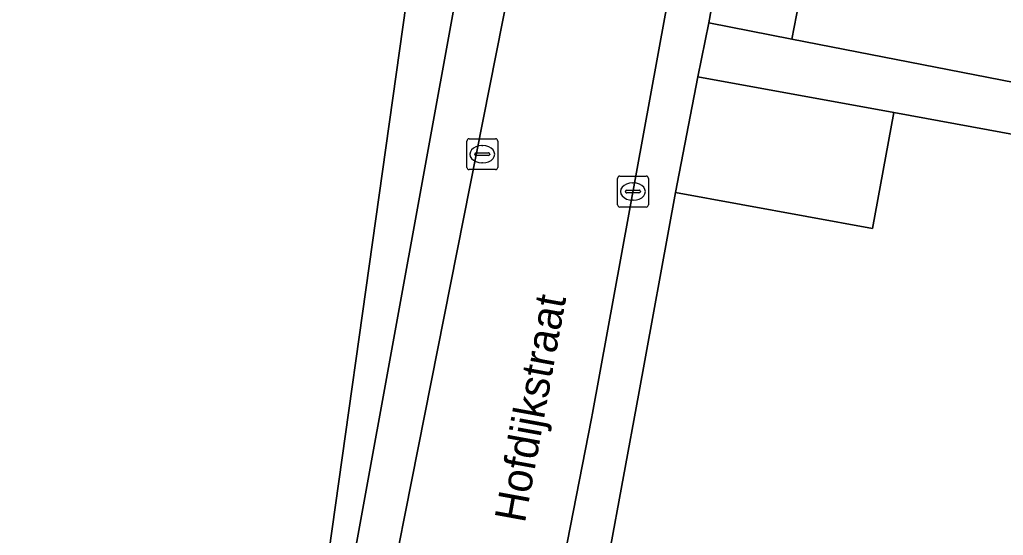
# Model space of a CAD drawing. Extents: x 161402 to 161933, y 381647 to 382315.
# Drawn here: x 161806.67 to 161838.49, y 381966.66 to 381983.35 of the extents above; entities that cross this region are included whole.
import ezdxf

# ---------------------------------------------------------------- set-up
doc = ezdxf.new("R2010")
doc.units = 0
for name, color, linetype in [('IMGEO_Erf', 7, 'Continuous'), ('IMGEO_Groenvoorziening', 7, 'Continuous'), ('IMGEO_Kolk', 7, 'Continuous'), ('IMGEO_Muur', 7, 'Continuous'), ('IMGEO_Openbare_ruimte_label', 7, 'Continuous'), ('IMGEO_Pand', 7, 'Continuous'), ('IMGEO_Parkeervlak_gesloten', 7, 'Continuous'), ('IMGEO_Rijbaan_lokaal_gesloten', 7, 'Continuous'), ('IMGEO_Rijbaan_lokaal_open', 7, 'Continuous'), ('IMGEO_Voetpad_open', 7, 'Continuous')]:
    doc.layers.add(name, color=color, linetype=linetype)

msp = doc.modelspace()

# ---------------------------------------------------------------- linework, layer by layer
at = {"layer": 'IMGEO_Erf'}
for points in [[(161781.596, 381964.647), (161815.795, 381959.903), (161829.294, 382055.793), (161829.439, 382055.781), (161829.897, 382055.72), (161832.064, 382072.53), (161836.652, 382071.701), (161840.585, 382094.002)], [(161839.466, 381979.518), (161834.946, 381980.346), (161834.257, 381976.588), (161827.883, 381977.756), (161826.684, 381971.203), (161825.719, 381965.932), (161832.204, 381964.716), (161838.276, 381963.578), (161838.779, 381966.265)]]:
    msp.add_lwpolyline(points, dxfattribs=at)
at = {"layer": 'IMGEO_Groenvoorziening'}
msp.add_lwpolyline([(161832.505, 382048.322), (161830.782, 382048.597), (161831.04, 382050.152), (161832.794, 382049.905), (161832.872, 382050.33), (161831.118, 382050.626), (161831.391, 382052.269), (161831.43, 382052.504), (161829.006, 382052.887), (161829.439, 382055.781), (161829.294, 382055.793), (161815.795, 381959.903), (161816.367, 381959.82), (161816.701, 381961.668), (161822.827, 381995.34)], close=True, dxfattribs=at)
at = {"layer": 'IMGEO_Kolk'}
for p, q in [((161821.134, 381978.571), (161821.134, 381979.423)), ((161821.209, 381979.497), (161822.061, 381979.497)), ((161822.135, 381979.423), (161822.135, 381978.571)), ((161821.393, 381978.991), (161821.393, 381979.003)), ((161821.436, 381979.04), (161821.834, 381979.04)), ((161821.622, 381979.277), (161821.647, 381979.277)), ((161821.877, 381979.003), (161821.877, 381978.991)), ((161821.831, 381978.954), (161821.433, 381978.954)), ((161821.645, 381978.717), (161821.62, 381978.717)), ((161822.061, 381978.497), (161821.209, 381978.497)), ((161826.008, 381977.362), (161826.008, 381978.214)), ((161826.083, 381978.288), (161826.935, 381978.288)), ((161826.496, 381978.068), (161826.521, 381978.068)), ((161827.009, 381978.214), (161827.009, 381977.362)), ((161826.267, 381977.782), (161826.267, 381977.794)), ((161826.705, 381977.745), (161826.307, 381977.745)), ((161826.31, 381977.831), (161826.708, 381977.831)), ((161826.751, 381977.794), (161826.751, 381977.782)), ((161826.519, 381977.508), (161826.494, 381977.508)), ((161826.935, 381977.288), (161826.083, 381977.288))]:
    msp.add_line(p, q, dxfattribs=at)
for points in [[(161821.134, 381978.571), (161821.134, 381979.423)], [(161821.209, 381979.497), (161822.061, 381979.497)], [(161822.135, 381979.423), (161822.135, 381978.571)], [(161822.061, 381978.497), (161821.209, 381978.497)], [(161826.008, 381977.362), (161826.008, 381978.214)], [(161826.083, 381978.288), (161826.935, 381978.288)], [(161827.009, 381978.214), (161827.009, 381977.362)], [(161826.935, 381977.288), (161826.083, 381977.288)]]:
    msp.add_lwpolyline(points, dxfattribs=at)
for centre, radius, start, end in [((161821.211, 381979.421), 0.0765, 91.552, 178.448), ((161821.211, 381979.421), 0.0765, 91.552, 178.448), ((161822.059, 381979.421), 0.0765, 1.552, 88.448), ((161822.059, 381979.421), 0.0765, 1.552, 88.448), ((161821.433, 381979), 0.0403, 85.8775, 175.7526), ((161821.43, 381978.99), 0.0366, 178.938, 274.7102), ((161821.834, 381978.997), 0.043, 264.8664, 352.4533), ((161821.838, 381979.002), 0.0386, 1.7309, 96.639), ((161821.211, 381978.573), 0.0765, 181.552, 268.448), ((161821.211, 381978.573), 0.0765, 181.552, 268.448), ((161822.059, 381978.573), 0.0765, 271.552, 358.448), ((161822.059, 381978.573), 0.0765, 271.552, 358.448), ((161826.085, 381978.212), 0.0765, 91.552, 178.448), ((161826.085, 381978.212), 0.0765, 91.552, 178.448), ((161826.933, 381978.212), 0.0765, 1.552, 88.448), ((161826.933, 381978.212), 0.0765, 1.552, 88.448), ((161826.307, 381977.791), 0.0403, 85.8775, 175.7526), ((161826.304, 381977.781), 0.0366, 178.938, 274.7102), ((161826.708, 381977.788), 0.043, 264.8664, 352.4533), ((161826.712, 381977.793), 0.0386, 1.7309, 96.639), ((161826.085, 381977.364), 0.0765, 181.552, 268.448), ((161826.085, 381977.364), 0.0765, 181.552, 268.448), ((161826.933, 381977.364), 0.0765, 271.552, 358.448), ((161826.933, 381977.364), 0.0765, 271.552, 358.448)]:
    msp.add_arc(centre, radius, start, end, dxfattribs=at)
for centre, major_axis, ratio, start_param, end_param in [((161821.621, 381978.997), (-0.387, 0.002), 0.722429, 4.712389, 7.853982), ((161821.646, 381978.997), (-0.39, 0.002), 0.717154, 1.570796, 4.712389), ((161826.495, 381977.788), (-0.387, 0.002), 0.722429, 4.712389, 7.853982), ((161826.52, 381977.788), (-0.39, 0.002), 0.717154, 1.570796, 4.712389)]:
    msp.add_ellipse(centre, major_axis=major_axis, ratio=ratio, start_param=start_param, end_param=end_param, dxfattribs=at)
at = {"layer": 'IMGEO_Muur'}
for points in [[(161827.883, 381977.756), (161826.684, 381971.203)], [(161826.684, 381971.203), (161825.719, 381965.932)]]:
    msp.add_lwpolyline(points, dxfattribs=at)
at = {"layer": 'IMGEO_Pand'}
msp.add_lwpolyline([(161827.883, 381977.756), (161834.257, 381976.588), (161834.946, 381980.346), (161828.609, 381981.506)], close=True, dxfattribs=at)
at = {"layer": 'IMGEO_Parkeervlak_gesloten'}
msp.add_lwpolyline([(161834.75, 381987.369), (161832.631, 381987.778), (161831.646, 381982.721), (161846.863, 381979.756), (161850.336, 381979.079), (161853.869, 381978.391), (161856.229, 381977.931), (161857.213, 381983.04)], close=True, dxfattribs=at)
at = {"layer": 'IMGEO_Rijbaan_lokaal_gesloten'}
msp.add_lwpolyline([(161834.474, 381994.007), (161830.987, 381994.574), (161828.968, 381983.243), (161831.646, 381982.721), (161832.631, 381987.778), (161834.75, 381987.369), (161857.213, 381983.04), (161856.229, 381977.931), (161861.321, 381976.94), (161861.636, 381978.805), (161862.491, 381983.458), (161857.448, 381984.357), (161864.341, 382023.003)], dxfattribs=at)
at = {"layer": 'IMGEO_Rijbaan_lokaal_open'}
for points in [[(161859.869, 382107.508), (161855.583, 382102.928), (161847.522, 382094.137), (161844.797, 382079.199), (161841.729, 382061.924), (161839.275, 382047.946), (161836.784, 382033.46), (161833.899, 382016.966), (161830.695, 382000), (161827.554, 381983.498), (161825.196, 381970.616), (161825.164, 381970.44), (161822.54, 381956.991), (161822.45, 381956.505), (161823.681, 381955.575), (161824.173, 381957.682), (161825.719, 381965.932), (161826.684, 381971.203), (161827.883, 381977.756), (161828.609, 381981.506), (161828.968, 381983.243), (161830.987, 381994.574), (161831.954, 382000), (161840.202, 382046.042)], [(161830.73, 382029.273), (161829.195, 382020.232), (161827.39, 382010.57), (161825.499, 382000), (161825.157, 381998.089), (161824.386, 381993.913), (161817.254, 381957.834), (161817.094, 381956.896), (161816.977, 381956.412), (161822.45, 381956.505), (161822.54, 381956.991), (161825.164, 381970.44), (161825.196, 381970.616), (161827.554, 381983.498), (161830.695, 382000), (161833.899, 382016.966), (161836.784, 382033.46)]]:
    msp.add_lwpolyline(points, dxfattribs=at)
msp.add_lwpolyline([(161827.39, 382010.57), (161829.195, 382020.232), (161830.73, 382029.273), (161834.543, 382050.384), (161834.774, 382051.699), (161833.171, 382051.969), (161832.872, 382050.33), (161832.794, 382049.905), (161832.505, 382048.322), (161822.827, 381995.34), (161816.701, 381961.668), (161816.367, 381959.82), (161815.783, 381956.589), (161816.977, 381956.412), (161817.094, 381956.896), (161817.254, 381957.834), (161824.386, 381993.913), (161825.157, 381998.089), (161825.499, 382000)], close=True, dxfattribs=at)
at = {"layer": 'IMGEO_Voetpad_open'}
msp.add_lwpolyline([(161831.646, 381982.721), (161828.968, 381983.243), (161828.609, 381981.506), (161834.946, 381980.346), (161839.466, 381979.518), (161839.486, 381979.628), (161844.674, 381978.618), (161846.563, 381978.219), (161846.863, 381979.756)], close=True, dxfattribs=at)

# ---------------------------------------------------------------- texts
at = {"layer": 'IMGEO_Openbare_ruimte_label'}
msp.add_text('Hofdijkstraat', height=1, rotation=79.6337, dxfattribs=at).set_placement((161823.01, 381967.036))

doc.saveas('drawing.dxf')
